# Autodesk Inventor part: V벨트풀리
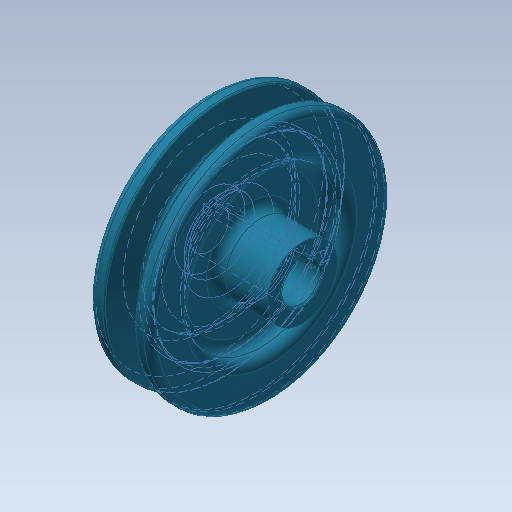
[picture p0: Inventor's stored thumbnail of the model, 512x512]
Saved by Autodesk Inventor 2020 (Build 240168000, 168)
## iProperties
Created: 2015-11
Part Number: V벨트풀리
Material: 강철, 탄소
Document SubType Name: Modeling
Designer: mduedu
Density: 1 g/cm^3
Appearance: 터키옥색
Author: mduedu
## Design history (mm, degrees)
sketch "스케치1"
  geometry: L1 (-9.5, 0)-(9.5, 0); L2 (0, 0)-(0, 37.7); L3 (-4.825, 37.7)-(-9.5, 37.7); L4 (-9.5, 37.7)-(-9.5, 0); L5 (0, 28.7)-(-2.074, 28.7); L6 (-2.074, 28.7)-(-4.825, 37.7); L7 (4.825, 37.7)-(9.5, 37.7); L8 (9.5, 37.7)-(9.5, 0); L9 (0, 28.7)-(2.074, 28.7); L10 (2.074, 28.7)-(4.825, 37.7); L11 (-9.5, 35)-(9.5, 35); 3 further points
  constraints: 22 end point, 7 point on line, 4 perpendicular, 3 symmetric about line, 1 coincident, 1 horizontal, 1 horizontal alignment, 1 midpoint, 1 vertical
  dimensions: "d0" = 19 distance of L1.start L1.end; "d2" = 75.4 diameter of L2.end L1 (derived); "d3" = 34 deg angle of L10 L6; "d4" = 6.3 distance between parallel lines of L11 L9; "d5" = 2.7 distance between parallel lines of L7 L11; "d6" = 8 distance of point (4, 35) point (-4, 35); "d7" = 70 diameter of L11 L1
revolve "회전1" sketch "스케치1" stored, may be unused: angle "d8" = 90 deg
sketch "스케치2"
  geometry: C1 r 24 at (0, 0); C2 r 11 at (0, 0); 1 further point
  constraints: 2 centre point, 2 coincident
  dimensions: "d9" = 48 diameter of C1; "d10" = 22 diameter of C2
extrude "돌출1" cut sketch "스케치2" distance "d11" = 6; taper "d12" = 0 deg
extrude "돌출3" join sketch "스케치2" distance "d37" = 10; taper "d38" = 0 deg
fillet "모깎기1" dims "d13" = 3
fillet "모깎기2" dims "d14" = 3
fillet "모깎기3" dims "d15" = 1, "d16" = 0.5, "d17" = 2
hole "구멍1" diameter "d20" = 12; stored, may be unused: countersink angle "d24" = 90 deg, drill point angle "d26" = 118 deg; dims "d21" = 6, "d22" = 4, "d23" = 2, "d25" = 8, "d39" = 10, "d40" = 10
sketch "스케치3"
  geometry: L1 (-2, 0)-(2, 0); L2 (2, 0)-(2, 7.8); L3 (2, 7.8)-(-2, 7.8); L4 (-2, 7.8)-(-2, 0); 2 further points
  constraints: 8 end point, 2 parallel, 1 coincident, 1 horizontal, 1 midpoint, 1 perpendicular
  dimensions: "d27" = 4 distance of L2.end L3.end; "d29" = 7.8 distance of L3.end L1.start
extrude "돌출2" cut sketch "스케치3" extent not by distance; stored distance "d30" = 6; taper "d31" = 0 deg
chamfer "모따기1" distance "d32" = 0.5; stored, may be unused: second distance "d33" = 2, angle "d34" = 45 deg
node "작업 평면1"
sketch "스케치4"
  geometry: L1 (-19, 11)-(-19, -11) reference; 2 further points
  constraints: 1 horizontal alignment
  dimensions: "d41" = 25 distance from line of point (6, 0) L1
hole "구멍2" sketch "스케치4" at (6, 0) diameter "d42" = 2.459; stored, may be unused: countersink angle "d46" = 90 deg, drill point angle "d48" = 118 deg; dims "d43" = 6, "d44" = 4, "d45" = 2, "d47" = 8
node "솔리드1"
mirror "대칭1"
